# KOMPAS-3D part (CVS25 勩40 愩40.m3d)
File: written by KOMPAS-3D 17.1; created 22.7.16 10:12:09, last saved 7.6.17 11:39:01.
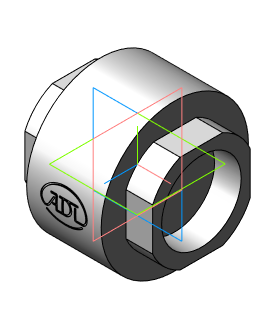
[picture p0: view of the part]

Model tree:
1. Операция без истории:2  (labels: Сталь 20  ГОСТ 1050-88)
